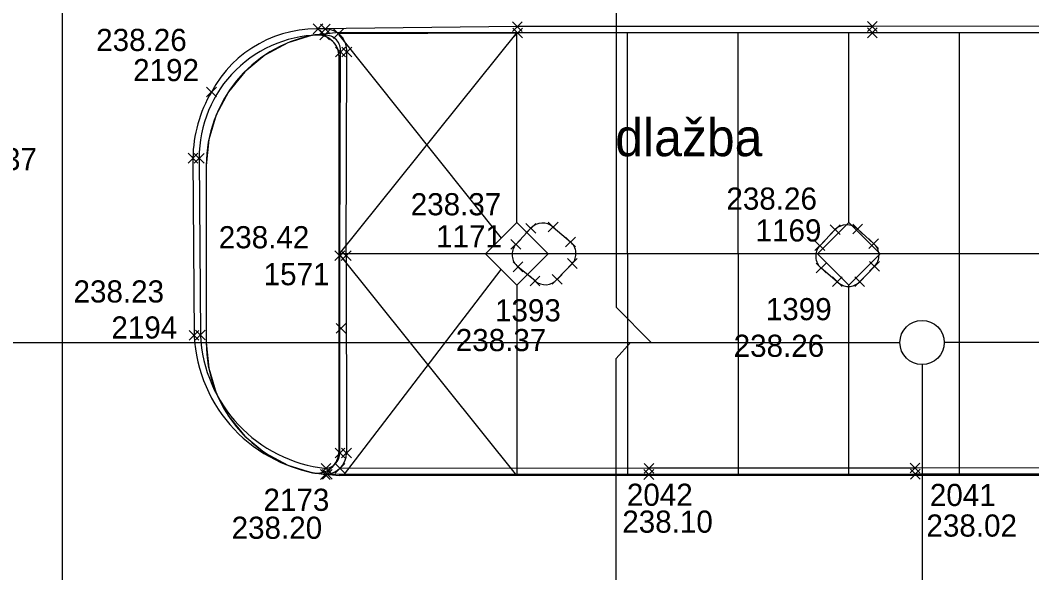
# Model space of a CAD drawing. Extents: x -264165 to -263733, y -1242319 to -1242245.
# Drawn here: x -263924.28 to -263901.43, y -1242289.18 to -1242276.71 of the extents above; entities that cross this region are included whole.
import ezdxf

# ---------------------------------------------------------------- set-up
doc = ezdxf.new("R2010")
doc.units = 0
for name, color, linetype in [('KFA_BOD_CISLO', 7, 'Continuous'), ('KFA_BOD_SYMBOL', 7, 'Continuous'), ('KFA_BOD_VYSKA', 7, 'Continuous'), ('KFA_SO_20-2_OBRUBNIKY_DOLNA_HRANA', 7, 'Continuous'), ('KFA_SO_20-2_OBRUBNIKY_HORNA_HRANA', 7, 'Continuous'), ('POPIS', 7, 'Continuous'), ('PROJEKT_OBRUBNIKY_KOMUNIKACIE', 7, 'Continuous'), ('PROJEKT_TDZ_VODOROVNE', 7, 'Continuous'), ('SITUACIA_DSP_2D', 7, 'Continuous')]:
    doc.layers.add(name, color=color, linetype=linetype)

msp = doc.modelspace()

# ---------------------------------------------------------------- linework, layer by layer
at = {"layer": 'KFA_BOD_SYMBOL'}
for p, q in [((-263917.667, -1242277.009), (-263917.446, -1242276.789)), ((-263917.446, -1242277.009), (-263917.667, -1242276.789)), ((-263917.503, -1242277.016), (-263917.282, -1242276.796)), ((-263917.282, -1242277.016), (-263917.503, -1242276.796)), ((-263917.203, -1242277.12), (-263916.981, -1242276.899)), ((-263916.981, -1242277.12), (-263917.203, -1242276.899)), ((-263913.167, -1242276.958), (-263912.946, -1242276.738)), ((-263912.946, -1242276.958), (-263913.167, -1242276.738)), ((-263913.159, -1242277.105), (-263912.938, -1242276.883)), ((-263912.938, -1242277.105), (-263913.159, -1242276.883)), ((-263905.145, -1242276.957), (-263904.924, -1242276.735)), ((-263904.924, -1242276.957), (-263905.145, -1242276.735)), ((-263905.145, -1242277.1), (-263904.924, -1242276.88)), ((-263904.924, -1242277.1), (-263905.145, -1242276.88)), ((-263917.516, -1242277.151), (-263917.295, -1242276.931)), ((-263917.295, -1242277.151), (-263917.516, -1242276.931)), ((-263917.16, -1242277.532), (-263916.939, -1242277.311)), ((-263916.939, -1242277.532), (-263917.16, -1242277.311)), ((-263917.018, -1242277.532), (-263916.796, -1242277.311)), ((-263916.796, -1242277.532), (-263917.018, -1242277.311)), ((-263920.073, -1242278.438), (-263919.852, -1242278.217)), ((-263919.852, -1242278.438), (-263920.073, -1242278.217)), ((-263920.492, -1242279.93), (-263920.27, -1242279.708)), ((-263920.27, -1242279.93), (-263920.492, -1242279.708)), ((-263920.351, -1242279.934), (-263920.129, -1242279.713)), ((-263920.129, -1242279.934), (-263920.351, -1242279.713)), ((-263912.861, -1242281.515), (-263912.639, -1242281.293)), ((-263912.639, -1242281.515), (-263912.861, -1242281.293)), ((-263912.356, -1242281.485), (-263912.135, -1242281.265)), ((-263912.135, -1242281.485), (-263912.356, -1242281.265)), ((-263905.985, -1242281.542), (-263905.764, -1242281.322)), ((-263905.764, -1242281.542), (-263905.985, -1242281.322)), ((-263905.476, -1242281.532), (-263905.255, -1242281.312)), ((-263905.255, -1242281.532), (-263905.476, -1242281.312)), ((-263913.199, -1242281.877), (-263912.978, -1242281.656)), ((-263912.978, -1242281.877), (-263913.199, -1242281.656)), ((-263911.964, -1242281.82), (-263911.742, -1242281.6)), ((-263911.742, -1242281.82), (-263911.964, -1242281.6)), ((-263906.334, -1242281.907), (-263906.112, -1242281.686)), ((-263906.112, -1242281.907), (-263906.334, -1242281.686)), ((-263905.117, -1242281.86), (-263904.896, -1242281.639)), ((-263904.896, -1242281.86), (-263905.117, -1242281.639)), ((-263917.175, -1242282.13), (-263916.954, -1242281.91)), ((-263916.954, -1242282.13), (-263917.175, -1242281.91)), ((-263917.031, -1242282.132), (-263916.81, -1242281.91)), ((-263916.81, -1242282.132), (-263917.031, -1242281.91)), ((-263913.15, -1242282.384), (-263912.929, -1242282.164)), ((-263912.929, -1242282.384), (-263913.15, -1242282.164)), ((-263911.924, -1242282.309), (-263911.703, -1242282.089)), ((-263911.703, -1242282.309), (-263911.924, -1242282.089)), ((-263905.096, -1242282.373), (-263904.875, -1242282.153)), ((-263904.875, -1242282.373), (-263905.096, -1242282.153)), ((-263906.302, -1242282.41), (-263906.081, -1242282.19)), ((-263906.081, -1242282.41), (-263906.302, -1242282.19)), ((-263912.766, -1242282.701), (-263912.545, -1242282.481)), ((-263912.545, -1242282.701), (-263912.766, -1242282.481)), ((-263912.264, -1242282.664), (-263912.042, -1242282.443)), ((-263912.042, -1242282.664), (-263912.264, -1242282.443)), ((-263905.938, -1242282.721), (-263905.716, -1242282.501)), ((-263905.716, -1242282.721), (-263905.938, -1242282.501)), ((-263905.431, -1242282.721), (-263905.209, -1242282.501)), ((-263905.209, -1242282.721), (-263905.431, -1242282.501)), ((-263920.468, -1242283.931), (-263920.247, -1242283.71)), ((-263920.247, -1242283.931), (-263920.468, -1242283.71)), ((-263920.323, -1242283.924), (-263920.102, -1242283.703)), ((-263920.102, -1242283.924), (-263920.323, -1242283.703)), ((-263917.148, -1242283.774), (-263916.927, -1242283.552)), ((-263916.927, -1242283.774), (-263917.148, -1242283.552)), ((-263917.171, -1242286.586), (-263916.95, -1242286.365)), ((-263916.95, -1242286.586), (-263917.171, -1242286.365)), ((-263917.024, -1242286.589), (-263916.803, -1242286.367)), ((-263916.803, -1242286.589), (-263917.024, -1242286.367)), ((-263917.486, -1242286.934), (-263917.264, -1242286.714)), ((-263917.264, -1242286.934), (-263917.486, -1242286.714)), ((-263917.172, -1242286.934), (-263916.951, -1242286.714)), ((-263916.951, -1242286.934), (-263917.172, -1242286.714)), ((-263910.191, -1242286.931), (-263909.97, -1242286.711)), ((-263909.97, -1242286.931), (-263910.191, -1242286.711)), ((-263904.181, -1242286.927), (-263903.959, -1242286.705)), ((-263903.959, -1242286.927), (-263904.181, -1242286.705)), ((-263917.5, -1242287.072), (-263917.279, -1242286.85)), ((-263917.279, -1242287.072), (-263917.5, -1242286.85)), ((-263917.457, -1242287.069), (-263917.236, -1242286.847)), ((-263917.236, -1242287.069), (-263917.457, -1242286.847)), ((-263910.194, -1242287.072), (-263909.973, -1242286.85)), ((-263909.973, -1242287.072), (-263910.194, -1242286.85)), ((-263904.177, -1242287.066), (-263903.956, -1242286.845)), ((-263903.956, -1242287.066), (-263904.177, -1242286.845))]:
    msp.add_line(p, q, dxfattribs=at)
at = {"layer": 'KFA_SO_20-2_OBRUBNIKY_DOLNA_HRANA'}
for p, q in [((-263920.381, -1242279.819), (-263920.357, -1242283.82)), ((-263916.921, -1242282.021), (-263916.914, -1242286.478))]:
    msp.add_line(p, q, dxfattribs=at)
for points in [[(-263816.727, -1242276.824), (-263824.896, -1242276.832), (-263841.932, -1242276.838), (-263860.969, -1242276.825), (-263872.991, -1242276.822), (-263881, -1242276.818), (-263897.019, -1242276.831), (-263905.035, -1242276.846), (-263913.057, -1242276.848), (-263917.557, -1242276.899)], [(-263817.074, -1242276.98), (-263824.904, -1242276.976), (-263831.918, -1242276.976), (-263841.931, -1242276.979), (-263850.949, -1242276.976), (-263860.958, -1242276.969), (-263872.991, -1242276.965), (-263880.996, -1242276.964), (-263889.006, -1242276.968), (-263897.017, -1242276.976), (-263905.035, -1242276.99), (-263913.048, -1242276.994), (-263917.092, -1242277.009)], [(-263916.921, -1242282.021), (-263916.907, -1242277.421)], [(-263819.103, -1242286.786), (-263819.439, -1242286.959), (-263828.996, -1242286.962), (-263838.005, -1242286.965), (-263845.009, -1242286.967), (-263853.017, -1242286.968), (-263861.032, -1242286.966), (-263868.037, -1242286.96), (-263877.037, -1242286.952), (-263886.053, -1242286.951), (-263895.068, -1242286.953), (-263904.067, -1242286.955), (-263910.084, -1242286.961), (-263917.346, -1242286.958)], [(-263819.419, -1242286.819), (-263828.995, -1242286.822), (-263838.007, -1242286.821), (-263845.022, -1242286.826), (-263853.012, -1242286.818), (-263861.03, -1242286.825), (-263868.034, -1242286.816), (-263877.043, -1242286.812), (-263886.05, -1242286.81), (-263895.064, -1242286.807), (-263904.07, -1242286.816), (-263910.08, -1242286.821), (-263917.062, -1242286.824)]]:
    msp.add_lwpolyline(points, dxfattribs=at)
for centre, major_axis, ratio, start_param, end_param in [((-263917.588, -1242279.589), (0.314, 2.671), 0.99983, 0.044491, 1.199609), ((-263917.392, -1242277.392), (-0.282, 0.397), 0.993731, 4.038367, 5.665182), ((-263917.413, -1242279.844), (-1.549, -2.535), 0.998985, 4.724144, 5.251935), ((-263917.035, -1242283.654), (1.591, -2.921), 0.999744, 4.263872, 5.677925), ((-263917.401, -1242286.474), (0.476, 0.105), 0.999556, 4.519835, 6.05679)]:
    msp.add_ellipse(centre, major_axis=major_axis, ratio=ratio, start_param=start_param, end_param=end_param, dxfattribs=at)
at = {"layer": 'KFA_SO_20-2_OBRUBNIKY_HORNA_HRANA'}
for p, q in [((-263920.24, -1242279.823), (-263920.213, -1242283.813)), ((-263913.089, -1242281.766), (-263912.75, -1242281.404)), ((-263912.246, -1242281.375), (-263911.853, -1242281.71)), ((-263906.223, -1242281.796), (-263905.874, -1242281.432)), ((-263905.366, -1242281.422), (-263905.007, -1242281.749)), ((-263917.061, -1242286.475), (-263917.064, -1242282.02)), ((-263912.655, -1242282.591), (-263913.04, -1242282.274)), ((-263911.813, -1242282.199), (-263912.153, -1242282.553)), ((-263905.827, -1242282.611), (-263906.192, -1242282.3)), ((-263904.986, -1242282.263), (-263905.32, -1242282.611))]:
    msp.add_line(p, q, dxfattribs=at)
msp.add_lwpolyline([(-263917.064, -1242282.02), (-263917.05, -1242277.421)], dxfattribs=at)
for centre, major_axis, ratio, start_param, end_param in [((-263917.48, -1242279.8), (1.8, 2.093), 0.999889, 0.683272, 2.28924), ((-263917.396, -1242277.388), (0.304, -0.169), 0.999511, 0.412088, 2.104618), ((-263912.483, -1242281.65), (-0.352, -0.09), 0.999144, 3.750485, 5.288927), ((-263905.615, -1242281.688), (-0.328, 0.158), 0.999233, 4.409724, 5.953589), ((-263912.816, -1242281.996), (0.113, -0.339), 0.99904, 3.690203, 5.283501), ((-263912.075, -1242281.974), (0.184, 0.292), 0.999533, 4.565579, 6.146849), ((-263905.962, -1242282.033), (0.106, -0.337), 0.999696, 3.671878, 5.266515), ((-263905.237, -1242282.016), (-0.045, 0.35), 0.998977, 3.808068, 5.444516), ((-263912.423, -1242282.321), (0.241, -0.263), 0.999541, 4.831796, 6.402391), ((-263905.574, -1242282.362), (0.33, -0.132), 0.998852, 4.297842, 5.886145), ((-263917.037, -1242283.663), (2.034, -2.444), 0.999969, 4.065555, 5.482574), ((-263917.417, -1242286.471), (0.33, -0.133), 0.99963, 5.211726, 6.652587)]:
    msp.add_ellipse(centre, major_axis=major_axis, ratio=ratio, start_param=start_param, end_param=end_param, dxfattribs=at)
at = {"layer": 'PROJEKT_OBRUBNIKY_KOMUNIKACIE'}
for p, q in [((-263917.68, -1242277.043), (-263918.24, -1242277.216)), ((-263917.08, -1242276.982), (-263917.68, -1242277.043)), ((-263917.592, -1242277.033), (-263917.68, -1242277.043)), ((-263917.504, -1242277.039), (-263917.592, -1242277.033)), ((-263917.418, -1242277.06), (-263917.504, -1242277.039)), ((-263917.337, -1242277.096), (-263917.418, -1242277.06)), ((-263917.264, -1242277.145), (-263917.337, -1242277.096)), ((-263917.08, -1242276.982), (-263817.068, -1242276.982)), ((-263918.24, -1242277.216), (-263918.756, -1242277.494)), ((-263917.201, -1242277.207), (-263917.264, -1242277.145)), ((-263917.149, -1242277.279), (-263917.201, -1242277.207)), ((-263917.111, -1242277.359), (-263917.149, -1242277.279)), ((-263917.088, -1242277.445), (-263917.111, -1242277.359)), ((-263918.756, -1242277.494), (-263919.208, -1242277.867)), ((-263917.08, -1242277.533), (-263917.088, -1242277.445)), ((-263917.08, -1242286.432), (-263917.08, -1242277.533)), ((-263919.208, -1242277.867), (-263919.578, -1242278.321)), ((-263919.578, -1242278.321), (-263919.854, -1242278.838)), ((-263919.854, -1242278.838), (-263920.023, -1242279.399)), ((-263920.023, -1242279.399), (-263920.08, -1242279.982)), ((-263920.08, -1242279.982), (-263920.08, -1242283.982)), ((-263920.08, -1242283.982), (-263920.023, -1242284.565)), ((-263920.023, -1242284.565), (-263919.854, -1242285.126)), ((-263919.854, -1242285.126), (-263919.578, -1242285.644)), ((-263919.578, -1242285.644), (-263919.208, -1242286.098)), ((-263919.208, -1242286.098), (-263918.756, -1242286.471)), ((-263918.756, -1242286.471), (-263918.24, -1242286.749)), ((-263917.088, -1242286.52), (-263917.08, -1242286.432)), ((-263917.201, -1242286.757), (-263917.149, -1242286.685)), ((-263917.149, -1242286.685), (-263917.111, -1242286.605)), ((-263917.111, -1242286.605), (-263917.088, -1242286.52)), ((-263918.24, -1242286.749), (-263917.68, -1242286.922)), ((-263917.68, -1242286.922), (-263917.08, -1242286.982)), ((-263917.68, -1242286.922), (-263917.592, -1242286.932)), ((-263917.592, -1242286.932), (-263917.504, -1242286.926)), ((-263917.504, -1242286.926), (-263917.418, -1242286.905)), ((-263917.418, -1242286.905), (-263917.337, -1242286.869)), ((-263917.337, -1242286.869), (-263917.264, -1242286.819)), ((-263917.264, -1242286.819), (-263917.201, -1242286.757)), ((-263819.568, -1242286.982), (-263917.08, -1242286.982))]:
    msp.add_line(p, q, dxfattribs=at)
for points in [[(-263913.068, -1242281.275), (-263912.361, -1242281.982), (-263913.068, -1242282.689), (-263913.775, -1242281.982), (-263913.068, -1242281.275)], [(-263905.568, -1242281.275), (-263904.861, -1242281.982), (-263905.568, -1242282.689), (-263906.275, -1242281.982), (-263905.568, -1242281.275)]]:
    msp.add_lwpolyline(points, dxfattribs=at)
at = {"layer": 'PROJEKT_TDZ_VODOROVNE'}
for p, q in [((-263923.33, -1242296.482), (-263923.33, -1242254.982)), ((-263917.087, -1242277.034), (-263913.421, -1242281.629)), ((-263913.068, -1242276.982), (-263917.08, -1242281.982)), ((-263913.068, -1242281.275), (-263913.068, -1242276.982)), ((-263910.568, -1242281.982), (-263910.568, -1242276.982)), ((-263908.068, -1242281.982), (-263908.068, -1242276.982)), ((-263905.568, -1242281.275), (-263905.568, -1242276.982)), ((-263903.068, -1242281.982), (-263903.068, -1242276.982)), ((-263898.775, -1242281.982), (-263917.08, -1242281.982)), ((-263913.068, -1242286.982), (-263917.08, -1242281.982)), ((-263910.568, -1242281.982), (-263910.568, -1242286.982)), ((-263908.068, -1242281.982), (-263908.068, -1242286.982)), ((-263903.068, -1242286.982), (-263903.068, -1242281.982)), ((-263916.984, -1242286.982), (-263913.421, -1242282.336)), ((-263913.068, -1242282.689), (-263913.068, -1242286.982)), ((-263905.568, -1242286.982), (-263905.568, -1242282.689))]:
    msp.add_line(p, q, dxfattribs=at)
at = {"layer": 'SITUACIA_DSP_2D'}
for p, q in [((-263910.824, -1242271.473), (-263910.824, -1242283.187)), ((-263917.08, -1242286.432), (-263917.08, -1242277.533)), ((-263920.08, -1242279.982), (-263920.08, -1242283.982)), ((-263910.824, -1242283.187), (-263910.029, -1242283.982)), ((-263946.608, -1242283.982), (-263908.955, -1242283.982)), ((-263946.608, -1242283.982), (-263904.413, -1242283.982)), ((-263910.824, -1242284.343), (-263910.499, -1242283.982)), ((-263871.324, -1242283.982), (-263903.413, -1242283.982)), ((-263910.824, -1242292.492), (-263910.824, -1242284.343)), ((-263903.913, -1242284.482), (-263903.913, -1242292.347))]:
    msp.add_line(p, q, dxfattribs=at)
for points in [[(-263913.068, -1242281.275), (-263912.361, -1242281.982), (-263913.068, -1242282.689), (-263913.775, -1242281.982)], [(-263905.568, -1242281.275), (-263904.861, -1242281.982), (-263905.568, -1242282.689), (-263906.275, -1242281.982)]]:
    msp.add_lwpolyline(points, close=True, dxfattribs=at)
msp.add_circle((-263903.913, -1242283.982), 0.5, dxfattribs=at)
for centre, radius, start, end in [((-263917.08, -1242279.982), 3, 101.537, 180), ((-263917.58, -1242277.533), 0.5, 0, 101.537), ((-263917.08, -1242283.982), 3, 180, 258.463), ((-263917.58, -1242286.432), 0.5, 258.463, 0)]:
    msp.add_arc(centre, radius, start, end, dxfattribs=at)

# ---------------------------------------------------------------- texts
at = {"layer": 'KFA_BOD_CISLO'}
for s, p in [('2192', (-263921.732, -1242278.081)), ('1169', (-263907.673, -1242281.701)), ('1171', (-263914.889, -1242281.833)), ('1571', (-263918.785, -1242282.689)), ('1393', (-263913.559, -1242283.505)), ('1399', (-263907.441, -1242283.479)), ('2194', (-263922.224, -1242283.893)), ('2042', (-263910.58, -1242287.67)), ('2041', (-263903.736, -1242287.674)), ('2173', (-263918.788, -1242287.784))]:
    msp.add_text(s, height=0.5, dxfattribs=at).set_placement(p)
at = {"layer": 'KFA_BOD_VYSKA'}
for s, p in [('238.26', (-263922.567, -1242277.4)), ('238.37', (-263925.952, -1242280.092)), ('238.26', (-263908.332, -1242280.983)), ('238.37', (-263915.462, -1242281.11)), ('238.42', (-263919.798, -1242281.855)), ('238.23', (-263923.079, -1242283.079)), ('238.37', (-263914.445, -1242284.177)), ('238.26', (-263908.168, -1242284.306)), ('238.10', (-263910.684, -1242288.277)), ('238.02', (-263903.813, -1242288.365)), ('238.20', (-263919.508, -1242288.415))]:
    msp.add_text(s, height=0.5, dxfattribs=at).set_placement(p)
at = {"layer": 'POPIS'}
msp.add_text('dlažba', height=0.8438, dxfattribs=at).set_placement((-263910.843, -1242279.775))

doc.saveas('drawing.dxf')
